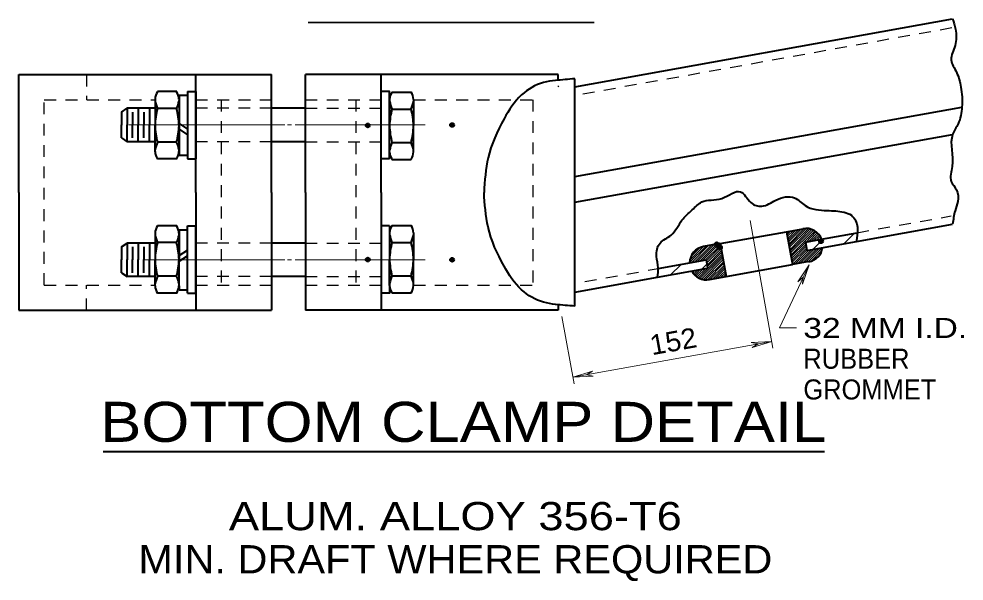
# Model space of a CAD drawing. Extents: x 312583 to 312854, y 144419 to 144597.
# Drawn here: x 312622.55 to 312658.39, y 144524.49 to 144545.82 of the extents above; entities that cross this region are included whole.
import ezdxf
from ezdxf.enums import TextEntityAlignment as Align

# ---------------------------------------------------------------- set-up
doc = ezdxf.new("R2010")
doc.units = 0
doc.header["$LTSCALE"] = 0.3
doc.header["$PDMODE"] = 32
doc.header["$PDSIZE"] = 0.15
doc.linetypes.add('SHORT_DASHED', pattern=[2.7, 1.5, -1.2])
doc.layers.add('1', color=7, linetype='Continuous', lineweight=40)

msp = doc.modelspace()

# ---------------------------------------------------------------- linework, layer by layer
at = {"layer": '1', "lineweight": 35}
for p, q in [((312633.5181, 144545.6748), (312644.3613, 144545.6748)), ((312651.6656, 144537.6964), (312651.7193, 144537.7578)), ((312651.6733, 144537.6274), (312651.8266, 144537.7731)), ((312651.6886, 144537.5584), (312651.9263, 144537.7884)), ((312651.704, 144537.4894), (312652.026, 144537.8114)), ((312651.7116, 144537.4128), (312652.1256, 144537.8268)), ((312651.727, 144537.3438), (312652.233, 144537.8498)), ((312651.7423, 144537.2748), (312652.325, 144537.8651)), ((312651.75, 144537.2058), (312652.4093, 144537.8651)), ((312651.7653, 144537.1368), (312652.486, 144537.8574)), ((312651.7806, 144537.0601), (312652.5626, 144537.8498)), ((312651.7883, 144536.9911), (312652.624, 144537.8268)), ((312651.8036, 144536.9221), (312652.6776, 144537.7961)), ((312651.819, 144536.8531), (312652.7313, 144537.7654)), ((312652.4016, 144537.3514), (312652.7773, 144537.7348)), ((312652.7006, 144537.4051), (312652.9076, 144537.6121)), ((312652.8003, 144537.4204), (312652.9383, 144537.5661)), ((312652.9076, 144537.4434), (312652.969, 144537.5048)), ((312647.9856, 144536.5694), (312648.6066, 144537.1981)), ((312648.001, 144536.6691), (312648.507, 144537.1751)), ((312648.0316, 144536.7841), (312648.3766, 144537.1291)), ((312648.07, 144536.5771), (312648.7063, 144537.2134)), ((312648.1696, 144536.5924), (312648.8136, 144537.2288)), ((312648.2693, 144536.6078), (312648.9133, 144537.2518)), ((312648.3766, 144536.6308), (312649.013, 144537.2671)), ((312648.4763, 144536.6461), (312649.1126, 144537.2901)), ((312648.576, 144536.6614), (312649.151, 144537.2364)), ((312648.6143, 144536.6231), (312649.1586, 144537.1674)), ((312648.6296, 144536.5541), (312649.174, 144537.0984)), ((312648.645, 144536.4774), (312649.1816, 144537.0218)), ((312651.8266, 144536.7841), (312652.3786, 144537.3284)), ((312651.842, 144536.7151), (312652.394, 144537.2594)), ((312651.8573, 144536.6461), (312652.4016, 144537.1904)), ((312651.865, 144536.5694), (312652.417, 144537.1214)), ((312651.8803, 144536.5004), (312652.4323, 144537.0524)), ((312651.9723, 144536.5081), (312652.5013, 144537.0371)), ((312652.072, 144536.5234), (312652.6086, 144537.0601)), ((312652.1716, 144536.5464), (312652.7083, 144537.0754)), ((312652.279, 144536.5618), (312652.808, 144537.0984)), ((312652.3786, 144536.5848), (312652.9076, 144537.1138)), ((312652.4783, 144536.6001), (312653.0073, 144537.1291)), ((312652.5933, 144536.6308), (312653.0073, 144537.0448)), ((312648.323, 144535.9944), (312649.2123, 144536.8838)), ((312648.3766, 144535.9714), (312649.22, 144536.8148)), ((312648.4456, 144535.9484), (312649.2353, 144536.7458)), ((312648.507, 144535.9254), (312649.2506, 144536.6768)), ((312648.6526, 144536.4084), (312649.197, 144536.9528)), ((312652.7543, 144536.7074), (312652.9306, 144536.8838)), ((312648.139, 144536.1478), (312648.2846, 144536.2858)), ((312648.1773, 144536.1018), (312648.3843, 144536.3088)), ((312648.2233, 144536.0634), (312648.484, 144536.3241)), ((312648.2693, 144536.0251), (312648.5836, 144536.3394)), ((312648.5836, 144535.9254), (312649.266, 144536.6001)), ((312648.6603, 144535.9178), (312649.2736, 144536.5311)), ((312648.7523, 144535.9331), (312649.289, 144536.4621)), ((312648.8596, 144535.9484), (312649.3043, 144536.3931)), ((312648.9593, 144535.9638), (312649.312, 144536.3241)), ((312648.07, 144536.2398), (312648.0776, 144536.2474)), ((312648.1083, 144536.1938), (312648.1773, 144536.2704)), ((312649.059, 144535.9868), (312649.3273, 144536.2474)), ((312649.1586, 144536.0021), (312649.3426, 144536.1784)), ((312649.2583, 144536.0174), (312649.3503, 144536.1094)), ((312649.358, 144536.0328), (312649.3656, 144536.0404))]:
    msp.add_line(p, q, dxfattribs=at)
at = {"layer": '1'}
for p, q in [((312643.631, 144543.2394), (312657.96, 144545.8154)), ((312622.5476, 144539.2298), (312622.5476, 144543.7071)), ((312629.256, 144539.2298), (312629.256, 144543.7071)), ((312632.131, 144539.2298), (312632.131, 144543.7071)), ((312633.4113, 144539.2298), (312633.4113, 144543.7071)), ((312636.2863, 144539.2298), (312636.2863, 144543.7071)), ((312642.9946, 144543.4848), (312642.9946, 144543.7071)), ((312643.631, 144534.9211), (312643.631, 144543.5461)), ((312627.715, 144542.7718), (312627.715, 144541.7828)), ((312628.5353, 144543.0554), (312627.807, 144543.0554)), ((312628.6196, 144542.7794), (312628.6196, 144542.9251)), ((312628.6196, 144542.9251), (312628.6196, 144540.6481)), ((312628.6196, 144542.9251), (312628.9416, 144542.9251)), ((312628.6196, 144542.7794), (312628.6196, 144541.7904)), ((312628.9416, 144543.0554), (312628.9416, 144540.5024)), ((312628.9416, 144543.0554), (312629.256, 144543.0554)), ((312629.256, 144543.0554), (312629.256, 144540.5024)), ((312636.2863, 144540.5024), (312636.2863, 144543.0554)), ((312636.6083, 144542.7641), (312636.6083, 144541.7751)), ((312636.6926, 144543.0401), (312637.421, 144543.0401)), ((312637.513, 144542.7564), (312637.513, 144541.7751)), ((312627.715, 144542.4268), (312626.6493, 144542.4268)), ((312627.071, 144542.4268), (312627.071, 144541.7828)), ((312627.5003, 144542.4268), (312627.5003, 144541.7828)), ((312628.5353, 144542.4114), (312627.807, 144542.4114)), ((312633.4113, 144542.4268), (312632.131, 144542.4268)), ((312636.6926, 144542.3961), (312637.421, 144542.3961)), ((312643.631, 144539.8354), (312658.3126, 144542.4728)), ((312626.4346, 144542.2734), (312626.4346, 144541.7828)), ((312626.8563, 144542.2734), (312626.8563, 144541.7828)), ((312627.2856, 144542.2734), (312627.2856, 144541.7828)), ((312626.4346, 144541.2998), (312626.4346, 144541.7904)), ((312626.8563, 144541.2998), (312626.8563, 144541.7904)), ((312627.071, 144541.1464), (312627.071, 144541.7904)), ((312627.2856, 144541.2998), (312627.2856, 144541.7904)), ((312627.5003, 144541.1464), (312627.5003, 144541.7904)), ((312627.715, 144540.7784), (312627.715, 144541.7904)), ((312628.6196, 144541.8441), (312628.9416, 144541.6294)), ((312628.6196, 144540.7784), (312628.6196, 144541.7904)), ((312636.6083, 144540.7631), (312636.6083, 144541.7751)), ((312637.513, 144540.7708), (312637.513, 144541.7828)), ((312628.6196, 144541.6294), (312628.9416, 144541.4224)), ((312643.631, 144538.8618), (312657.96, 144541.4301)), ((312627.715, 144541.1464), (312626.6493, 144541.1464)), ((312628.5353, 144541.1388), (312627.7993, 144541.1388)), ((312633.4113, 144541.1464), (312632.131, 144541.1464)), ((312636.6926, 144541.1234), (312637.421, 144541.1234)), ((312628.6196, 144540.6481), (312628.6196, 144540.7784)), ((312628.6196, 144540.6481), (312628.9416, 144540.6481)), ((312628.5353, 144540.5024), (312627.807, 144540.5024)), ((312628.9416, 144540.5024), (312629.256, 144540.5024)), ((312636.6083, 144540.5024), (312636.2863, 144540.5024)), ((312636.6926, 144540.4871), (312637.421, 144540.4871)), ((312622.5476, 144539.2298), (312622.5476, 144534.7601)), ((312629.256, 144539.2298), (312629.256, 144534.7601)), ((312632.131, 144539.2298), (312632.131, 144534.7601)), ((312633.4113, 144539.2298), (312633.4113, 144534.7601)), ((312636.2863, 144539.2298), (312636.2863, 144534.7601)), ((312628.5353, 144537.9648), (312627.807, 144537.9648)), ((312628.6196, 144537.8114), (312628.6196, 144537.6888)), ((312628.6196, 144537.8114), (312628.9416, 144537.8114)), ((312628.6196, 144535.5421), (312628.6196, 144537.8114)), ((312628.9416, 144537.9648), (312629.256, 144537.9648)), ((312628.9416, 144535.4118), (312628.9416, 144537.9648)), ((312629.256, 144535.4118), (312629.256, 144537.9648)), ((312636.6083, 144537.9648), (312636.2863, 144537.9648)), ((312636.2863, 144537.9648), (312636.2863, 144535.4118)), ((312636.6926, 144537.9801), (312637.421, 144537.9801)), ((312649.1433, 144537.2978), (312651.658, 144537.7424)), ((312651.658, 144537.7424), (312652.2866, 144537.8574)), ((312651.658, 144537.7424), (312651.8803, 144536.4928)), ((312654.3106, 144537.3744), (312657.96, 144538.0261)), ((312627.715, 144537.6811), (312627.715, 144536.6691)), ((312628.6196, 144537.6888), (312628.6196, 144536.6768)), ((312636.6083, 144537.6964), (312636.6083, 144536.6844)), ((312637.513, 144537.6964), (312637.513, 144536.6844)), ((312652.3786, 144537.3438), (312652.992, 144537.4588)), ((312652.4323, 144537.0294), (312654.3106, 144537.3668)), ((312652.992, 144537.4588), (312654.3413, 144537.7041)), ((312626.4346, 144537.1674), (312626.4346, 144536.6691)), ((312627.715, 144537.3131), (312626.6493, 144537.3131)), ((312626.8563, 144537.1674), (312626.8563, 144536.6691)), ((312627.071, 144537.3131), (312627.071, 144536.6691)), ((312627.2856, 144537.1674), (312627.2856, 144536.6691)), ((312627.5003, 144537.3131), (312627.5003, 144536.6691)), ((312628.5353, 144537.3284), (312627.7993, 144537.3284)), ((312628.6196, 144536.8378), (312628.9416, 144537.0448)), ((312633.4113, 144537.3131), (312632.131, 144537.3131)), ((312636.6926, 144537.3361), (312637.421, 144537.3361)), ((312649.1356, 144537.2901), (312648.5146, 144537.1751)), ((312649.1433, 144537.2978), (312649.3656, 144536.0404)), ((312652.3786, 144537.3438), (312652.4323, 144537.0294)), ((312626.4346, 144536.1861), (312626.4346, 144536.6844)), ((312626.8563, 144536.1861), (312626.8563, 144536.6844)), ((312627.071, 144536.0404), (312627.071, 144536.6844)), ((312627.2856, 144536.1861), (312627.2856, 144536.6844)), ((312627.5003, 144536.0404), (312627.5003, 144536.6844)), ((312627.715, 144535.6954), (312627.715, 144536.6768)), ((312628.6196, 144536.6231), (312628.9416, 144536.8301)), ((312628.6196, 144535.6878), (312628.6196, 144536.6768)), ((312636.6083, 144535.7031), (312636.6083, 144536.6844)), ((312637.513, 144535.7031), (312637.513, 144536.6921)), ((312646.7973, 144536.3471), (312648.6066, 144536.6691)), ((312648.6066, 144536.6691), (312648.6603, 144536.3548)), ((312646.7666, 144536.0174), (312648.6603, 144536.3548)), ((312649.3656, 144536.0404), (312651.8803, 144536.4928)), ((312652.509, 144536.6078), (312651.8803, 144536.4928)), ((312627.715, 144536.0404), (312626.6493, 144536.0404)), ((312628.5353, 144536.0558), (312627.807, 144536.0558)), ((312633.4113, 144536.0404), (312632.131, 144536.0404)), ((312636.6926, 144536.0711), (312637.421, 144536.0711)), ((312643.631, 144535.4501), (312646.7666, 144536.0174)), ((312648.737, 144535.9254), (312649.3656, 144536.0404)), ((312628.6196, 144535.6878), (312628.6196, 144535.5421)), ((312628.5353, 144535.4118), (312627.807, 144535.4118)), ((312628.6196, 144535.5421), (312628.9416, 144535.5421)), ((312628.9416, 144535.4118), (312629.256, 144535.4118)), ((312636.6926, 144535.4194), (312637.421, 144535.4194)), ((312642.9946, 144534.9748), (312642.9946, 144534.7601)), ((312625.7427, 144529.3994), (312653.0987, 144529.3994))]:
    msp.add_line(p, q, dxfattribs=at)
at = {"layer": '1', "linetype": 'SHORT_DASHED', "lineweight": 25}
for p, q in [((312643.9376, 144542.9711), (312657.9906, 144545.4934)), ((312625.1083, 144543.7071), (312625.1083, 144542.7488)), ((312623.506, 144542.7488), (312627.715, 144542.7488)), ((312623.506, 144535.7184), (312623.506, 144542.7488)), ((312629.256, 144542.7488), (312632.131, 144542.7488)), ((312630.2143, 144542.7488), (312630.2143, 144535.7184)), ((312633.4113, 144542.7488), (312636.2863, 144542.7488)), ((312635.328, 144542.7488), (312635.328, 144535.7184)), ((312637.513, 144542.7488), (312642.0363, 144542.7488)), ((312642.0363, 144542.7488), (312642.0363, 144535.7184)), ((312632.131, 144542.4268), (312629.256, 144542.4268)), ((312633.4113, 144542.4268), (312636.2863, 144542.4268)), ((312632.131, 144541.1464), (312629.256, 144541.1464)), ((312633.4113, 144541.1464), (312636.2863, 144541.1464)), ((312654.3413, 144537.7041), (312657.9063, 144538.3404)), ((312632.131, 144537.3131), (312629.256, 144537.3131)), ((312633.4113, 144537.3131), (312636.2863, 144537.3131)), ((312644.0143, 144535.8488), (312646.7973, 144536.3471)), ((312632.131, 144536.0404), (312629.256, 144536.0404)), ((312633.4113, 144536.0404), (312636.2863, 144536.0404)), ((312623.506, 144535.7184), (312627.715, 144535.7184)), ((312625.1083, 144534.7601), (312625.1083, 144535.7184)), ((312629.256, 144535.7184), (312632.131, 144535.7184)), ((312633.4113, 144535.7184), (312636.2863, 144535.7184)), ((312637.513, 144535.7184), (312642.0363, 144535.7184))]:
    msp.add_line(p, q, dxfattribs=at)
at = {"layer": '1', "lineweight": 25}
msp.add_line((312642.9946, 144543.2394), (312643.0253, 144543.2701), dxfattribs=at)
at = {"layer": '1', "lineweight": 13}
for p, q in [((312632.6293, 144541.7904), (312626.7106, 144541.7904)), ((312632.729, 144541.7904), (312632.8823, 144541.7904)), ((312633.0203, 144541.7904), (312637.95, 144541.7904)), ((312650.278, 144538.1641), (312651.1443, 144533.3264)), ((312652.6546, 144537.0678), (312653.061, 144537.4741)), ((312653.8276, 144537.2824), (312654.234, 144537.6811)), ((312632.6293, 144536.6768), (312627.2473, 144536.6768)), ((312632.729, 144536.6768), (312632.8823, 144536.6768)), ((312633.0203, 144536.6768), (312637.95, 144536.6768)), ((312647.265, 144536.1018), (312647.6636, 144536.5004)), ((312648.4456, 144536.3164), (312648.6373, 144536.5081)), ((312652.5243, 144536.4851), (312652.0899, 144535.8417)), ((312652.5243, 144536.4851), (312652.2637, 144535.7526)), ((312652.0899, 144535.8417), (312652.2859, 144536.0156)), ((312652.2637, 144535.7526), (312652.2859, 144536.0156)), ((312643.1403, 144534.5224), (312643.6003, 144531.9694)), ((312643.5543, 144532.2224), (312651.0983, 144533.5794)), ((312651.0983, 144533.5794), (312650.324, 144533.5334)), ((312650.324, 144533.5334), (312650.5846, 144533.4874)), ((312651.0983, 144533.5794), (312650.3623, 144533.3494)), ((312650.3623, 144533.3494), (312650.5846, 144533.4874)), ((312643.5543, 144532.2224), (312644.298, 144532.4524)), ((312644.298, 144532.4524), (312644.068, 144532.3144)), ((312643.5543, 144532.2224), (312644.3286, 144532.2608)), ((312644.3286, 144532.2608), (312644.068, 144532.3144))]:
    msp.add_line(p, q, dxfattribs=at)
at = {"layer": '1'}
for points in [[(312622.5476, 144543.7071), (312629.256, 144543.7071), (312632.131, 144543.7071)], [(312642.9946, 144543.7071), (312636.2863, 144543.7071), (312633.4113, 144543.7071)], [(312636.6083, 144540.5024), (312636.6083, 144543.0554), (312636.2863, 144543.0554)], [(312626.4346, 144542.2734), (312626.6493, 144542.4268), (312626.6493, 144541.7828)], [(312626.4346, 144541.2998), (312626.6493, 144541.1464), (312626.6493, 144541.7904)], [(312636.6083, 144537.9648), (312636.6083, 144535.4118), (312636.2863, 144535.4118)], [(312626.4346, 144537.1674), (312626.6493, 144537.3131), (312626.6493, 144536.6691)], [(312626.4346, 144536.1861), (312626.6493, 144536.0404), (312626.6493, 144536.6844)], [(312622.5476, 144534.7601), (312629.256, 144534.7601), (312632.131, 144534.7601)], [(312642.9946, 144534.7601), (312636.2863, 144534.7601), (312633.4113, 144534.7601)]]:
    msp.add_lwpolyline(points, dxfattribs=at)
at = {"layer": '1', "lineweight": 35}
for points in [[(312652.5013, 144537.3668), (312652.8233, 144537.6964), (312652.831, 144537.6964)], [(312652.601, 144537.3898), (312652.8693, 144537.6581), (312652.8693, 144537.6581)]]:
    msp.add_lwpolyline(points, dxfattribs=at)
at = {"layer": '1', "lineweight": 13}
msp.add_lwpolyline([(312652.5243, 144536.4851), (312651.3976, 144534.0984), (312652.0339, 144534.0984)], dxfattribs=at)
at = {"layer": '1'}
for centre, radius, start, end in [((312628.2376, 144542.7567), 0.5262, 145.8703, 178.33743), ((312628.0926, 144542.7567), 0.5262, 1.66257, 34.1297), ((312637.1328, 144542.744), 0.5262, 145.8703, 178.33743), ((312636.9878, 144542.744), 0.5262, 1.66257, 34.1297), ((312630.4285, 144541.7094), 2.7192, 164.99798, 178.595), ((312629.1852, 144543.0108), 1.5067, 191.77014, 203.36365), ((312627.145, 144543.0108), 1.5067, 336.63635, 348.22986), ((312625.9017, 144541.7094), 2.7192, 1.405, 15.00202), ((312639.3237, 144541.6967), 2.7192, 164.99798, 178.595), ((312638.0804, 144542.998), 1.5067, 191.77014, 203.36365), ((312634.7968, 144541.6967), 2.7192, 1.405, 15.00202), ((312636.0402, 144542.998), 1.5067, 336.63635, 348.22986), ((312630.4285, 144541.8428), 2.7192, 181.405, 195.00202), ((312625.9017, 144541.8428), 2.7192, 344.99798, 358.595), ((312639.3237, 144541.83), 2.7192, 181.405, 195.00202), ((312634.7968, 144541.83), 2.7192, 344.99798, 358.595), ((312629.1852, 144540.5414), 1.5067, 156.63635, 168.22986), ((312627.145, 144540.5414), 1.5067, 11.77014, 23.36365), ((312638.0804, 144540.5286), 1.5067, 156.63635, 168.22986), ((312636.0402, 144540.5286), 1.5067, 11.77014, 23.36365), ((312628.2376, 144540.7955), 0.5262, 181.66257, 214.1297), ((312628.0926, 144540.7955), 0.5262, 325.8703, 358.33743), ((312637.1328, 144540.7827), 0.5262, 181.66257, 214.1297), ((312636.9878, 144540.7827), 0.5262, 325.8703, 358.33743), ((312628.2376, 144537.6692), 0.5262, 145.8703, 178.33743), ((312628.0926, 144537.6692), 0.5262, 1.66257, 34.1297), ((312637.1328, 144537.6819), 0.5262, 145.8703, 178.33743), ((312636.9878, 144537.6819), 0.5262, 1.66257, 34.1297), ((312652.399, 144537.2318), 0.6361, 20.92751, 100.40744), ((312629.1852, 144537.9232), 1.5067, 191.77014, 203.36365), ((312627.145, 144537.9232), 1.5067, 336.63635, 348.22986), ((312638.0804, 144537.936), 1.5067, 191.77014, 203.36365), ((312636.0402, 144537.936), 1.5067, 336.63635, 348.22986), ((312630.4285, 144536.6219), 2.7192, 164.99798, 178.595), ((312625.9017, 144536.6219), 2.7192, 1.405, 15.00202), ((312639.3237, 144536.6346), 2.7192, 164.99798, 178.595), ((312634.7968, 144536.6346), 2.7192, 1.405, 15.00202), ((312648.6214, 144536.5517), 0.6361, 99.90643, 179.34108), ((312652.399, 144537.2318), 0.6361, 279.9552, 351.41104), ((312630.4285, 144536.7552), 2.7192, 181.405, 195.00202), ((312625.9017, 144536.7552), 2.7192, 344.99798, 358.595), ((312639.3237, 144536.768), 2.7192, 181.405, 195.00202), ((312634.7968, 144536.768), 2.7192, 344.99798, 358.595), ((312629.1852, 144535.4538), 1.5067, 156.63635, 168.22986), ((312627.145, 144535.4538), 1.5067, 11.77014, 23.36365), ((312638.0804, 144535.4666), 1.5067, 156.63635, 168.22986), ((312636.0402, 144535.4666), 1.5067, 11.77014, 23.36365), ((312648.6214, 144536.5517), 0.6361, 208.60683, 280.45563), ((312628.2376, 144535.7079), 0.5262, 181.66257, 214.1297), ((312628.0926, 144535.7079), 0.5262, 325.8703, 358.33743), ((312637.1328, 144535.7207), 0.5262, 181.66257, 214.1297), ((312636.9878, 144535.7207), 0.5262, 325.8703, 358.33743)]:
    msp.add_arc(centre, radius, start, end, dxfattribs=at)
for points in [[(312657.96, 144545.8154), (312658.0673, 144545.4321), (312658.052, 144544.8034), (312657.9063, 144544.2591), (312658.1056, 144543.7914), (312658.2743, 144543.2318), (312658.3126, 144542.4728), (312658.167, 144541.8364), (312657.96, 144541.4301), (312657.9446, 144540.2188), (312657.9063, 144539.6514), (312658.1056, 144539.3294), (312658.1516, 144538.8848), (312658.052, 144538.5398), (312657.96, 144538.0261)], [(312643.631, 144543.5461), (312642.895, 144543.4771), (312642.4426, 144543.4004), (312641.6146, 144542.9328), (312640.9476, 144542.0204), (312640.342, 144540.5484), (312640.1886, 144539.2298)], [(312643.631, 144534.9211), (312642.895, 144534.9824), (312642.4426, 144535.0668), (312641.6146, 144535.5344), (312640.9476, 144536.4391), (312640.342, 144537.9188), (312640.1886, 144539.2298)], [(312646.7666, 144536.0174), (312646.7973, 144536.3701), (312646.7283, 144536.8071), (312646.8663, 144537.3131), (312647.2803, 144537.6121), (312647.6943, 144538.1794), (312648.0853, 144538.5704), (312648.4456, 144538.8694), (312649.2046, 144539.0074), (312649.9176, 144539.2604), (312650.3086, 144538.8464), (312650.7226, 144538.7084), (312651.2516, 144538.9384), (312651.9646, 144539.0304), (312652.371, 144538.7314), (312653.199, 144538.5474), (312653.843, 144538.4784), (312654.119, 144538.3634), (312654.349, 144537.9111), (312654.3336, 144537.5738), (312654.3106, 144537.3744)]]:
    msp.add_spline(points, degree=3, dxfattribs=at)
for p in [(312635.7803, 144541.7751), (312638.9773, 144541.7904), (312652.969, 144537.3821), (312649.013, 144537.2671), (312649.0513, 144537.2288), (312649.0973, 144537.1828), (312649.1356, 144537.1444), (312635.7803, 144536.6844), (312638.9773, 144536.6768)]:
    msp.add_point(p, dxfattribs=at)

# ---------------------------------------------------------------- texts
for s, width, p in [('32 MM I.D.', 1.25, (312652.2986, 144533.7102)), ('RUBBER', 0.95, (312652.2986, 144532.5439)), ('GROMMET', 0.95, (312652.2986, 144531.3776))]:
    msp.add_text(s, height=0.76, dxfattribs=dict(at, width=width)).set_placement(p)
at = {"layer": '1', "width": 1.05}
msp.add_text('152', height=0.76, rotation=10.213, dxfattribs=at).set_placement((312646.5539, 144533.0542))
at = {"layer": '1'}
for s, height, width, p in [('BOTTOM CLAMP DETAIL', 1.52, 1.15, (312639.401, 144529.7691)), ('ALUM. ALLOY 356-T6', 1.07, 1.2, (312639.1, 144526.4187)), ('MIN. DRAFT WHERE REQUIRED', 1.07, 1.1, (312639.1, 144524.7814))]:
    msp.add_text(s, height=height, dxfattribs=dict(at, width=width)).set_placement(p, align=Align.CENTER)

doc.saveas('drawing.dxf')
